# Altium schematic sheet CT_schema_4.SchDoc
size 349 x 342 mm
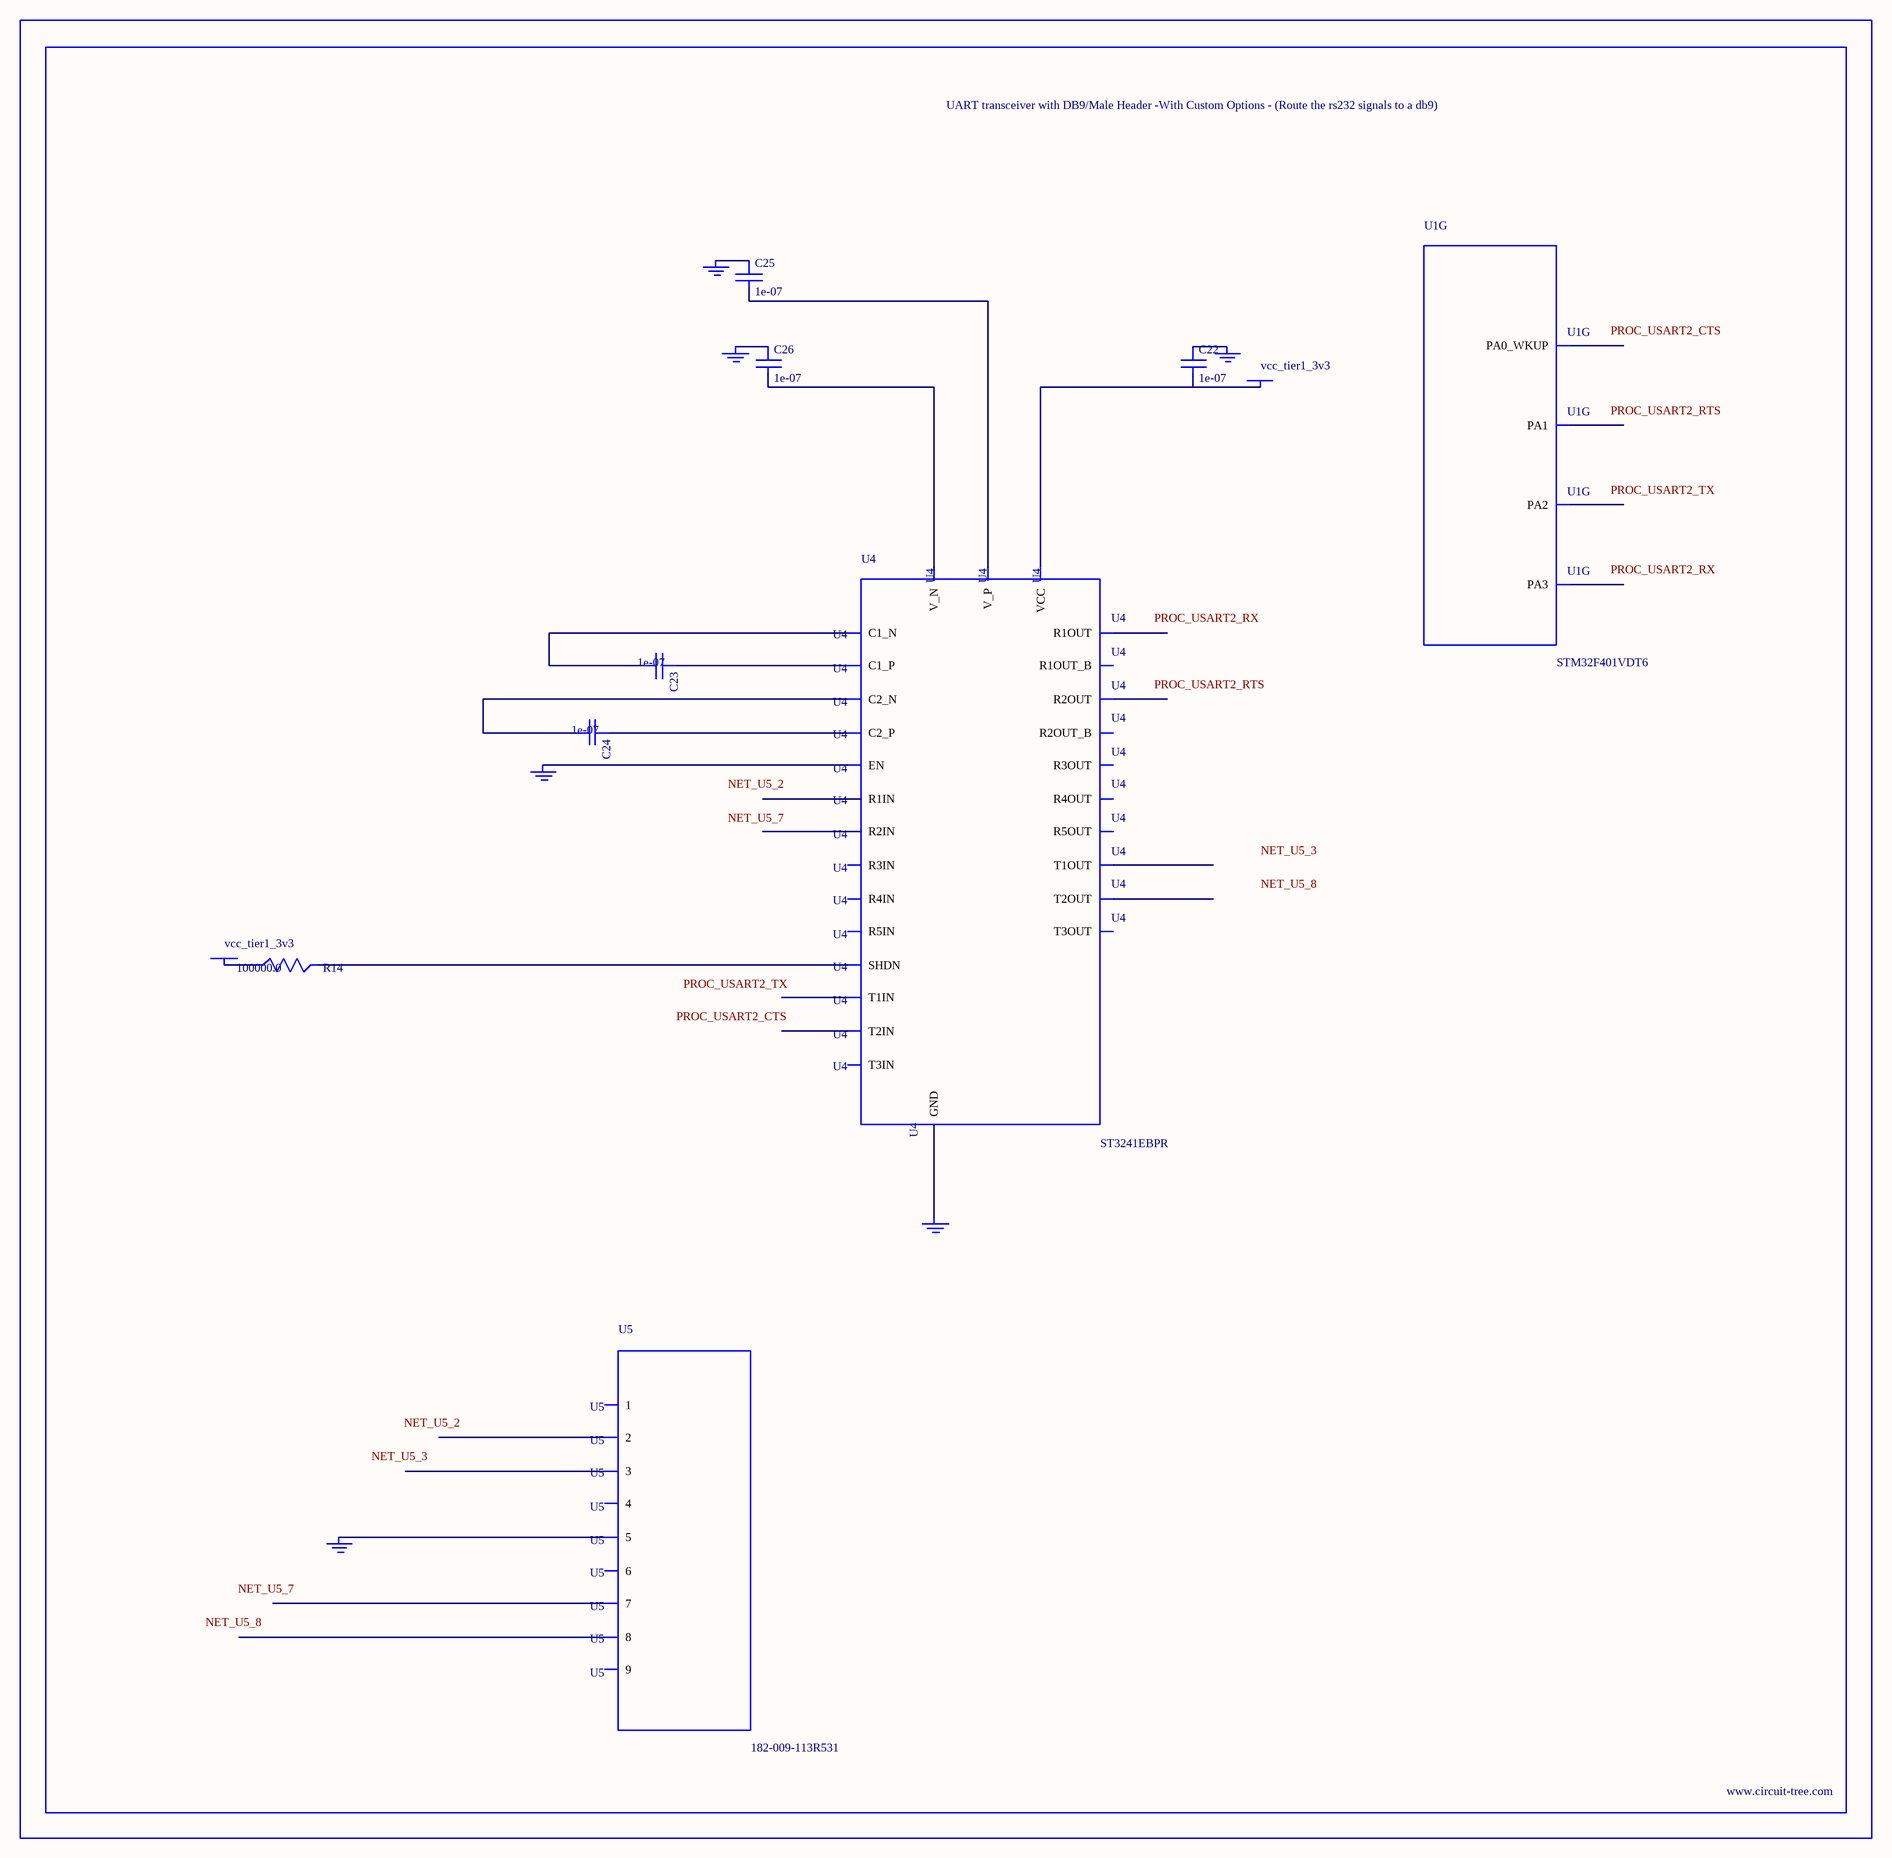
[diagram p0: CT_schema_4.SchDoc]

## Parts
BORDER3  (no value)
C22  1e-07  [C0402]
C23  1e-07  [C0402]
C24  1e-07  [C0402]
C25  1e-07  [C0402]
C26  1e-07  [C0402]
GND_INSTANCE_3_0  (no value)
GND_INSTANCE_3_1  (no value)
GND_INSTANCE_3_2  (no value)
GND_INSTANCE_3_3  (no value)
GND_INSTANCE_3_4  (no value)
GND_INSTANCE_3_5  (no value)
POWER_INSTANCE_3_0  vcc_tier1_3v3
POWER_INSTANCE_3_1  vcc_tier1_3v3
R14  100000.0  [R0603]
U1  STM32F401VDT6  [LQFP100]  (part G of 10)
U4  ST3241EBPR  [SSOP-28]
U5  182-009-113R531  [182-009-MALE]

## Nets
NetC22_1: C22.1 GND_INSTANCE_3_2.0(GND)
NetC22_2: C22.2 POWER_INSTANCE_3_1.0(PWR) U4.26(VCC)
NetC23_1: C23.1 U4.28(C1_P)
NetC23_2: C23.2 U4.24(C1_N)
NetC24_1: C24.1 U4.1(C2_P)
NetC24_2: C24.2 U4.2(C2_N)
NetC25_1: C25.1 GND_INSTANCE_3_3.0(GND)
NetC25_2: C25.2 U4.27(V_P)
NetC26_1: C26.1 GND_INSTANCE_3_0.0(GND)
NetC26_2: C26.2 U4.3(V_N)
NetGND_INSTANCE_3_1_0: GND_INSTANCE_3_1.0(GND) U4.23(EN)
NetGND_INSTANCE_3_4_0: GND_INSTANCE_3_4.0(GND) U4.25(GND)
NetGND_INSTANCE_3_5_0: GND_INSTANCE_3_5.0(GND) U5.5
NetPOWER_INSTANCE_3_0_0: POWER_INSTANCE_3_0.0(PWR) R14.1
NetR14_2: R14.2 U4.22(SHDN)

Not connected (* = marked no-connect by the designer): U1 23(PA0_WKUP) 24(PA1) 25(PA2) 26(PA3); U4 4(R1IN) 5(R2IN) 6(R3IN) 7(R4IN) 8(R5IN) 9(T1OUT) 10(T2OUT) 11(T3OUT) 12(T3IN) 13(T2IN) 14(T1IN) 15(R5OUT) 16(R4OUT) 17(R3OUT) 18(R2OUT) 19(R1OUT) 20(R2OUT_B) 21(R1OUT_B); U5 1 2 3 4 6 7 8 9

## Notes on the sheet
- Labels drawn without touching a wire or pin: NET_U5_2, NET_U5_3, NET_U5_7, NET_U5_8, PROC_USART2_CTS, PROC_USART2_RTS, PROC_USART2_RX, PROC_USART2_TX

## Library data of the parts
BORDER3 = BORDER_PAGE3
C22-C26 = C0402C104K3RACTU
GND_INSTANCE_3_0-GND_INSTANCE_3_5 = GND
POWER_INSTANCE_3_0 POWER_INSTANCE_3_1 = PWR
R14 = RC0603JR-07100KL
